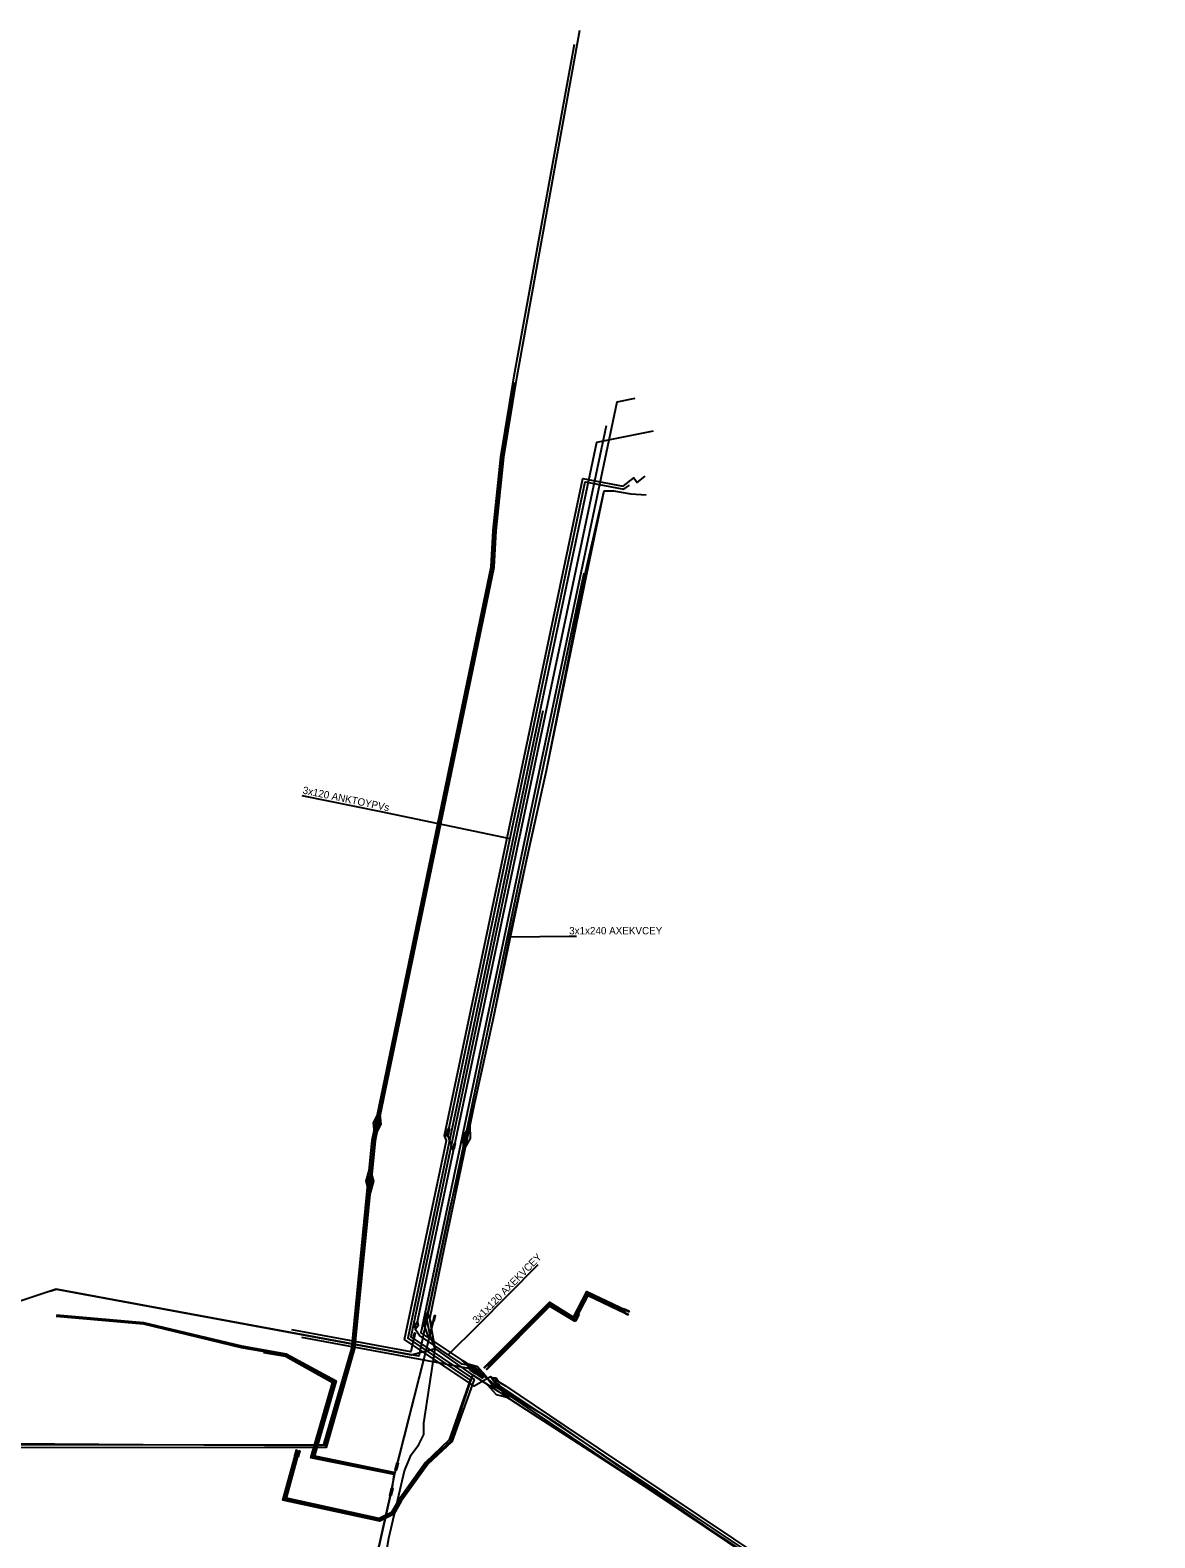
# Model space of a CAD drawing. Extents: x -739895 to -737975, y -1046419 to -1045728.
# Drawn here: x -739775.6 to -739622.9, y -1045932.9 to -1045728.3 of the extents above; entities that cross this region are included whole.
import ezdxf

# ---------------------------------------------------------------- set-up
doc = ezdxf.new("R2010")
doc.units = 0
for name, color, linetype in [('TR_SPOJKOVISTE_VN', 7, 'Continuous'), ('TRASA_KABELU_VN_PROVOZ', 7, 'Continuous'), ('TRASA_KABELU_VN_VYRAZENO', 7, 'Continuous'), ('VN_KABELOVE_VEDENI_PROVOZ', 7, 'Continuous'), ('VN_KABELOVE_VEDENI_VYRAZENO', 7, 'Continuous'), ('VN_POPIS_USEKU', 7, 'Continuous'), ('VN_SPOJKA_KONCOVKA', 7, 'Continuous')]:
    doc.layers.add(name, color=color, linetype=linetype)

msp = doc.modelspace()

# ---------------------------------------------------------------- linework, layer by layer
at = {"layer": 'TR_SPOJKOVISTE_VN'}
for points in [[(-739728.79, -1045878.43), (-739728.96, -1045876.62), (-739728.16, -1045874.98), (-739727.98, -1045876.79), (-739728.79, -1045878.43)], [(-739716.75, -1045880.31), (-739716.8, -1045878.49), (-739715.88, -1045876.92), (-739715.83, -1045878.74), (-739716.75, -1045880.31)], [(-739729.44, -1045886.27), (-739729.94, -1045884.52), (-739729.45, -1045882.77), (-739728.94, -1045884.52), (-739729.44, -1045886.27)], [(-739721.39, -1045905.87), (-739722.02, -1045904.16), (-739721.66, -1045902.38), (-739721.03, -1045904.09), (-739721.39, -1045905.87)], [(-739713.63, -1045911.07), (-739715.37, -1045910.54), (-739716.57, -1045909.17), (-739714.83, -1045909.7), (-739713.63, -1045911.07)], [(-739710.52, -1045914), (-739712.27, -1045913.51), (-739713.49, -1045912.17), (-739711.74, -1045912.66), (-739710.52, -1045914)]]:
    msp.add_lwpolyline(points, dxfattribs=at)
at = {"layer": 'TRASA_KABELU_VN_PROVOZ'}
msp.add_line((-739715.51, -1045910.8), (-739720.61, -1045907.24), dxfattribs=at)
for points in [[(-739709.83, -1045776.1), (-739711.48, -1045786.24), (-739712.51, -1045796.22), (-739712.81, -1045801.19), (-739728.47, -1045876.7), (-739728.93, -1045879), (-739729.44, -1045884.52), (-739731.72, -1045907.33), (-739735.53, -1045920.47), (-739760.21, -1045920.3), (-739808.4, -1045919.96)], [(-739716.31, -1045878.62), (-739715.23, -1045874.06), (-739712.65, -1045862.38), (-739710.42, -1045851.06), (-739705.46, -1045828.79), (-739702.34, -1045813.04), (-739700.26, -1045802.27), (-739697.64, -1045790.79)], [(-739720.61, -1045907.24), (-739721.25, -1045905.49), (-739721.53, -1045904.12), (-739721.73, -1045903.11), (-739718.56, -1045888.16), (-739716.31, -1045878.62)], [(-739749.46, -1046130.72), (-739747.74, -1046110.8), (-739746.29, -1046094.93), (-739744.66, -1046077.01), (-739743.67, -1046066.64), (-739743.52, -1046062.06), (-739742.17, -1046058.69), (-739741.63, -1046052.49), (-739742.18, -1046049.16), (-739740.75, -1046035.69), (-739739.45, -1046023.37), (-739738.11, -1046008.85), (-739736.59, -1045995.37), (-739734.39, -1045979.01), (-739732.13, -1045964.36), (-739729.33, -1045947.32), (-739726.88, -1045932.97), (-739724.75, -1045923.86), (-739723.84, -1045921.69), (-739722.8, -1045920.27), (-739722.13, -1045918.92), (-739722.13, -1045917.36), (-739720.61, -1045907.24)], [(-739715.51, -1045910.8), (-739718.52, -1045919.8), (-739721.73, -1045922.8), (-739725.34, -1045927.85), (-739726.4, -1045929.62), (-739728.16, -1045930.5), (-739741.02, -1045927.66), (-739739.32, -1045921.53)], [(-739679.47, -1045934.49), (-739684.15, -1045931.17), (-739691.19, -1045926.39), (-739696.83, -1045922.41), (-739703.42, -1045917.84), (-739706.19, -1045916.07), (-739709.21, -1045914.31), (-739712.5, -1045912.2), (-739713.45, -1045911.34), (-739715.1, -1045910.12), (-739716.1, -1045909.51)], [(-739715.51, -1045910.8), (-739712.01, -1045913.09), (-739711.27, -1045913.58), (-739692.68, -1045925.59), (-739676.1, -1045936.54)]]:
    msp.add_lwpolyline(points, dxfattribs=at)
at = {"layer": 'TRASA_KABELU_VN_VYRAZENO'}
msp.add_line((-739726.07, -1045924.21), (-739720.73, -1045903.19), dxfattribs=at)
for points in [[(-739772.84, -1045899.47), (-739772.02, -1045899.2), (-739723.85, -1045908.1), (-739720.61, -1045907.24)], [(-739713.44, -1045909.63), (-739705.06, -1045901.21), (-739701.71, -1045903.25), (-739699.91, -1045899.76), (-739694.74, -1045902.22)], [(-739772.03, -1045902.83), (-739760.16, -1045903.91), (-739746.91, -1045907.08), (-739740.85, -1045908.13), (-739734.27, -1045911.74), (-739736.82, -1045920.5), (-739737.22, -1045921.95), (-739726.07, -1045924.21)], [(-739766.16, -1046344.68), (-739766.11, -1046342.56), (-739763.2, -1046311.95), (-739761.68, -1046295.97), (-739758.86, -1046269.57), (-739755.83, -1046234.36), (-739752.98, -1046201.83), (-739751.88, -1046193.29), (-739749.29, -1046164.38), (-739748.1, -1046150.99), (-739745.33, -1046118.84), (-739744.68, -1046110.28), (-739743.44, -1046097.32), (-739741.73, -1046077.71), (-739740.43, -1046062.48), (-739746.54, -1046047.42), (-739743.96, -1046003.75), (-739743.52, -1046000.31), (-739739.5, -1045984.46), (-739726.54, -1045926.7), (-739726.07, -1045924.21)]]:
    msp.add_lwpolyline(points, dxfattribs=at)
at = {"layer": 'VN_KABELOVE_VEDENI_PROVOZ'}
msp.add_line((-739677.81, -1045935.55), (-739711.06, -1045913.27), dxfattribs=at)
for points in [[(-739728.26, -1045876.76), (-739712.59, -1045801.18), (-739712.31, -1045796.23), (-739711.28, -1045786.26), (-739709.48, -1045775.23), (-739700.94, -1045728.28)], [(-739729.67, -1045884.49), (-739729.13, -1045878.97), (-739712.99, -1045801.13), (-739712.71, -1045796.2), (-739711.67, -1045786.21), (-739709.88, -1045775.18), (-739701.69, -1045730.19)], [(-739690.99, -1045782.69), (-739698.7, -1045784.23), (-739724.31, -1045905.83), (-739715.83, -1045911.53), (-739718.67, -1045919.65), (-739721.91, -1045922.69), (-739725.52, -1045927.77), (-739726.51, -1045929.49), (-739728.2, -1045930.32), (-739740.77, -1045927.54), (-739739.12, -1045921.56)], [(-739712.48, -1045911.45), (-739713.08, -1045911.08), (-739715.28, -1045912.37), (-739724.76, -1045906.02), (-739719.07, -1045879.01), (-739719.33, -1045878.3), (-739700.55, -1045789.14), (-739695.09, -1045790.18), (-739693.64, -1045789.04), (-739693.15, -1045789.66), (-739692.07, -1045788.82)], [(-739718.84, -1045877.91), (-739700.23, -1045789.6), (-739694.99, -1045790.6), (-739694.23, -1045790.04)], [(-739726.88, -1045932.97), (-739724.75, -1045923.86), (-739723.84, -1045921.69), (-739722.8, -1045920.27), (-739722.13, -1045918.92), (-739722.13, -1045917.36), (-739720.61, -1045907.24), (-739721.32, -1045903.19), (-739719.31, -1045893.49), (-739716.22, -1045878.62), (-739715.23, -1045874.06), (-739712.65, -1045862.38), (-739708.07, -1045840.36), (-739705.46, -1045828.79), (-739700, -1045802.08), (-739697.63, -1045790.79), (-739696.39, -1045790.81), (-739694.05, -1045791.23), (-739691.94, -1045791.35)], [(-739705.97, -1045820.68), (-739723.87, -1045905.65), (-739715.29, -1045911.46), (-739718.31, -1045919.9), (-739721.57, -1045922.92), (-739725.2, -1045927.98), (-739726.21, -1045929.73), (-739728.1, -1045930.68), (-739741.25, -1045927.81), (-739739.5, -1045921.45)], [(-739728.26, -1045876.76), (-739728.73, -1045879.04), (-739731.52, -1045907.24), (-739735.38, -1045920.67), (-739893.37, -1045920.72)], [(-739718.84, -1045877.91), (-739718.92, -1045878.27), (-739718.14, -1045880.39), (-739723.13, -1045904.09)], [(-739895.4, -1045920.32), (-739735.68, -1045920.27), (-739731.92, -1045907.17), (-739729.67, -1045884.49)], [(-739711.06, -1045913.27), (-739712.91, -1045912.13), (-739714.02, -1045910.65), (-739715.62, -1045909.6), (-739716.94, -1045909.36), (-739722.73, -1045905.45), (-739723.28, -1045904.68), (-739723.13, -1045904.09)], [(-739712.48, -1045911.45), (-739711.06, -1045912.31), (-739703.12, -1045917.63), (-739675.42, -1045936.19), (-739675.24, -1045936.79), (-739672.85, -1045938.41), (-739674.93, -1045945.64), (-739676.79, -1045951.92), (-739661, -1045956.6), (-739626.51, -1045971.24), (-739624.84, -1045971.6), (-739622.9, -1045976), (-739625.32, -1045988.46), (-739627.85, -1046000.1), (-739630.21, -1046009.4), (-739632.57, -1046018.7), (-739637.28, -1046037.28), (-739639.1, -1046058.3), (-739640.93, -1046079.32), (-739642.75, -1046100.36), (-739644.58, -1046121.39), (-739644.83, -1046127.08), (-739645.75, -1046136.49)]]:
    msp.add_lwpolyline(points, dxfattribs=at)
at = {"layer": 'VN_KABELOVE_VEDENI_VYRAZENO'}
for p, q in [((-739697.4, -1045781.98), (-739718.01, -1045879.77)), ((-739700.4, -1045802), (-739716.52, -1045878.56)), ((-739725.8, -1045923.26), (-739720.73, -1045903.19)), ((-739714.49, -1045910.97), (-739715.38, -1045910.38))]:
    msp.add_line(p, q, dxfattribs=at)
for points in [[(-739693.48, -1045778.3), (-739695.91, -1045778.79), (-739722.53, -1045905.1), (-739716.55, -1045909.11)], [(-739716.52, -1045878.56), (-739722.79, -1045908.29), (-739772.02, -1045899.2), (-739778.96, -1045901.51), (-739795.38, -1045901.81), (-739796.1, -1045901.18), (-739799.87, -1045901.25), (-739805.65, -1045910.93), (-739806.27, -1045910.94)], [(-739713.61, -1045909.52), (-739705.08, -1045900.96), (-739701.79, -1045902.97), (-739700, -1045899.5), (-739694.68, -1045902.04)], [(-739701.34, -1045902.98), (-739699.82, -1045900.02), (-739694.81, -1045902.42)], [(-739772.01, -1045902.65), (-739760.19, -1045903.7), (-739746.88, -1045906.89), (-739740.8, -1045907.94), (-739734.02, -1045911.61), (-739736.96, -1045921.81), (-739726, -1045924.06), (-739725.8, -1045923.26)], [(-739713.28, -1045909.75), (-739705.03, -1045901.47), (-739701.63, -1045903.54), (-739701.34, -1045902.98)], [(-739723.44, -1045905.56), (-739723.89, -1045907.68), (-739740.03, -1045904.7)], [(-739715.38, -1045910.38), (-739716.03, -1045909.94), (-739738.69, -1045905.76)], [(-739726.54, -1045926.7), (-739726.4, -1045926.06), (-739726.14, -1045924.36), (-739737.48, -1045922.1), (-739734.52, -1045911.88), (-739740.91, -1045908.33), (-739743.87, -1045907.81)], [(-739665.72, -1045954.37), (-739675.79, -1045951.38), (-739672.21, -1045939.3), (-739675.59, -1045937.04), (-739675.76, -1045936.44), (-739712.2, -1045912.02)], [(-739726.54, -1045926.7), (-739739.5, -1045984.46), (-739743.09, -1045999.69), (-739743.12, -1046000), (-739745.75, -1046026.62), (-739747.62, -1046047.51), (-739740.43, -1046062.48), (-739741.73, -1046077.71), (-739743.97, -1046103.38)]]:
    msp.add_lwpolyline(points, dxfattribs=at)
at = {"layer": 'VN_POPIS_USEKU'}
for points in [[(-739738.69, -1045832.15), (-739727.96, -1045834.36), (-739710.44, -1045838.02)], [(-739710.36, -1045851.37), (-739702.4, -1045851.27), (-739701.4, -1045851.27)], [(-739718.78, -1045908.05), (-739714.75, -1045904.09), (-739706.59, -1045895.85)]]:
    msp.add_lwpolyline(points, dxfattribs=at)
at = {"layer": 'VN_SPOJKA_KONCOVKA'}
for points in [[(-739728.07, -1045876.28), (-739728.27, -1045877.27), (-739728.45, -1045877.24), (-739728.25, -1045876.24)], [(-739718.65, -1045877.43), (-739718.85, -1045878.42), (-739719.03, -1045878.39), (-739718.83, -1045877.39)], [(-739716.72, -1045879.03), (-739716.51, -1045878.04), (-739716.33, -1045878.08), (-739716.54, -1045879.07)], [(-739717.88, -1045879.39), (-739718.06, -1045880.21), (-739718.14, -1045880.19), (-739717.96, -1045879.37), (-739717.94, -1045879.38), (-739718.1, -1045880.14), (-739718.07, -1045880.15), (-739717.91, -1045879.39)], [(-739729.53, -1045884), (-739729.64, -1045885), (-739729.82, -1045884.98), (-739729.71, -1045883.98)], [(-739720.87, -1045903.56), (-739720.67, -1045902.75), (-739720.58, -1045902.77), (-739720.79, -1045903.58), (-739720.81, -1045903.58), (-739720.62, -1045902.82), (-739720.65, -1045902.81), (-739720.84, -1045903.57)], [(-739701.03, -1045902.57), (-739701.49, -1045903.47), (-739701.65, -1045903.39), (-739701.19, -1045902.48)], [(-739695.15, -1045902.21), (-739694.4, -1045902.58), (-739694.43, -1045902.65), (-739695.18, -1045902.29), (-739695.17, -1045902.26), (-739694.47, -1045902.6), (-739694.46, -1045902.58), (-739695.16, -1045902.24)], [(-739695.01, -1045901.83), (-739694.26, -1045902.19), (-739694.29, -1045902.26), (-739695.05, -1045901.91), (-739695.04, -1045901.88), (-739694.33, -1045902.21), (-739694.32, -1045902.19), (-739695.03, -1045901.86)], [(-739723.56, -1045905.94), (-739723.39, -1045905.12), (-739723.31, -1045905.14), (-739723.48, -1045905.96), (-739723.51, -1045905.95), (-739723.35, -1045905.19), (-739723.37, -1045905.18), (-739723.54, -1045905.94)], [(-739716.85, -1045908.85), (-739716.16, -1045909.32), (-739716.21, -1045909.39), (-739716.9, -1045908.92), (-739716.89, -1045908.9), (-739716.24, -1045909.34), (-739716.22, -1045909.31), (-739716.87, -1045908.88)], [(-739713.31, -1045909.27), (-739713.9, -1045909.86), (-739713.96, -1045909.8), (-739713.37, -1045909.21), (-739713.35, -1045909.23), (-739713.9, -1045909.78), (-739713.88, -1045909.8), (-739713.33, -1045909.25)], [(-739715.01, -1045910.73), (-739715.85, -1045910.17), (-739715.75, -1045910.02), (-739714.91, -1045910.58)], [(-739714.79, -1045910.72), (-739714.1, -1045911.18), (-739714.15, -1045911.25), (-739714.84, -1045910.79), (-739714.82, -1045910.76), (-739714.18, -1045911.2), (-739714.16, -1045911.18), (-739714.81, -1045910.74)], [(-739712.97, -1045909.5), (-739713.56, -1045910.09), (-739713.62, -1045910.03), (-739713.03, -1045909.44), (-739713.01, -1045909.46), (-739713.56, -1045910.01), (-739713.54, -1045910.03), (-739712.99, -1045909.48)], [(-739711.9, -1045912.27), (-739712.6, -1045911.82), (-739712.55, -1045911.75), (-739711.85, -1045912.2), (-739711.87, -1045912.23), (-739712.52, -1045911.8), (-739712.54, -1045911.82), (-739711.88, -1045912.25)], [(-739739.65, -1045921.82), (-739739.43, -1045921.01), (-739739.35, -1045921.03), (-739739.56, -1045921.84), (-739739.59, -1045921.84), (-739739.39, -1045921.08), (-739739.42, -1045921.07), (-739739.62, -1045921.83)], [(-739739.26, -1045921.93), (-739739.04, -1045921.12), (-739738.96, -1045921.14), (-739739.18, -1045921.95), (-739739.21, -1045921.94), (-739739, -1045921.19), (-739739.03, -1045921.18), (-739739.23, -1045921.93)], [(-739725.59, -1045922.79), (-739725.83, -1045923.77), (-739726.01, -1045923.73), (-739725.76, -1045922.74)], [(-739726.75, -1045927.17), (-739726.52, -1045926.18), (-739726.34, -1045926.22), (-739726.57, -1045927.21)]]:
    msp.add_lwpolyline(points, close=True, dxfattribs=at)
for points in [[(-739723.01, -1045903.58), (-739722.89, -1045904.14), (-739723.25, -1045904.6), (-739723.36, -1045904.04), (-739723.01, -1045903.58)], [(-739712.94, -1045911.18), (-739712.36, -1045911.24), (-739712.03, -1045911.72), (-739712.61, -1045911.65), (-739712.94, -1045911.18)], [(-739710.62, -1045913.55), (-739711.19, -1045913.47), (-739711.51, -1045912.99), (-739710.94, -1045913.06), (-739710.62, -1045913.55)]]:
    msp.add_lwpolyline(points, dxfattribs=at)

# ---------------------------------------------------------------- texts
at = {"layer": 'VN_POPIS_USEKU'}
for s, rotation, p in [('3x120 ANKTOYPVs', 348.3307, (-739738.64, -1045831.9)), ('3x1x120 AXEKVCEY', 45.3065, (-739714.93, -1045903.92))]:
    msp.add_text(s, height=1, rotation=rotation, dxfattribs=at).set_placement(p)
msp.add_text('3x1x240 AXEKVCEY', height=1, dxfattribs=at).set_placement((-739702.4, -1045851.02))

doc.saveas('drawing.dxf')
